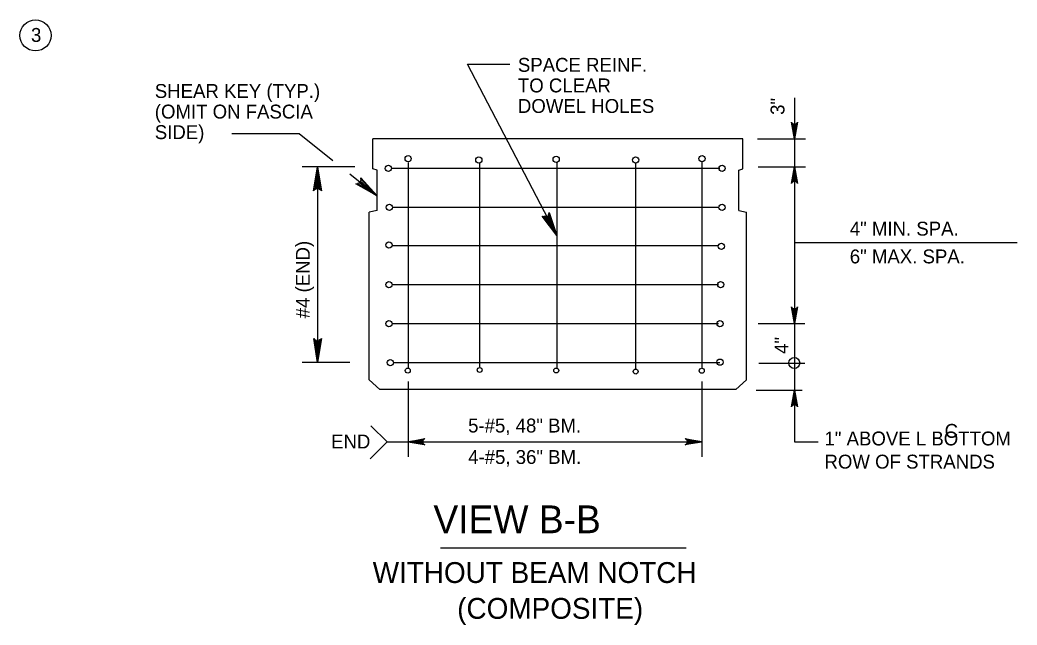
# Model space of a CAD drawing. Extents: x 639331 to 643089, y 299088 to 300975.
# Drawn here: x 639679.8 to 639895, y 300579.4 to 300710.1 of the extents above; entities that cross this region are included whole.
import ezdxf

# ---------------------------------------------------------------- set-up
doc = ezdxf.new("R2010")
doc.units = 0
doc.layers.add('1', color=7, linetype='Continuous')

msp = doc.modelspace()

# ---------------------------------------------------------------- linework, layer by layer
at = {"layer": '1'}
for p, q in [((639776.37, 300700.5), (639785.5, 300700.5)), ((639795.67, 300663.54), (639776.37, 300700.5)), ((639846.94, 300693.26), (639846.94, 300684.09)), ((639725.57, 300685.53), (639740.08, 300685.53)), ((639740.08, 300685.53), (639747.37, 300679.72)), ((639835.81, 300684.39), (639755.98, 300684.39)), ((639755.98, 300677.92), (639755.98, 300684.39)), ((639835.81, 300677.92), (639835.81, 300684.39)), ((639838.97, 300684.39), (639849.34, 300684.39)), ((639846.94, 300684.39), (639846.94, 300678.37)), ((639752.08, 300678.37), (639740.75, 300678.37)), ((639744.05, 300678.37), (639744.05, 300636.13)), ((639756.88, 300677.62), (639755.98, 300677.92)), ((639760, 300678.07), (639830.85, 300678.07)), ((639763.58, 300679.28), (639763.58, 300634.92)), ((639778.98, 300679.13), (639778.98, 300635.07)), ((639795.67, 300679.28), (639795.67, 300634.92)), ((639812.66, 300679.13), (639812.66, 300634.77)), ((639826.98, 300679.43), (639826.98, 300634.92)), ((639834.91, 300677.62), (639835.81, 300677.92)), ((639839.12, 300678.37), (639849.34, 300678.37)), ((639846.94, 300678.37), (639846.94, 300644.55)), ((639751.01, 300676.82), (639756.88, 300672.13)), ((639756.88, 300668.9), (639756.88, 300677.62)), ((639834.91, 300668.9), (639834.91, 300677.62)), ((639760.22, 300669.65), (639830.7, 300669.65)), ((639756.88, 300668.9), (639755.22, 300668.6)), ((639755.22, 300632.37), (639755.22, 300668.6)), ((639834.91, 300668.9), (639836.56, 300668.6)), ((639836.56, 300632.37), (639836.56, 300668.6)), ((639760.19, 300661.38), (639830.55, 300661.38)), ((639846.94, 300662), (639894.95, 300662)), ((639760.34, 300652.97), (639830.55, 300652.97)), ((639760.19, 300644.55), (639830.55, 300644.55)), ((639839.12, 300644.55), (639849.19, 300644.55)), ((639846.94, 300644.55), (639846.94, 300635.98)), ((639750.99, 300636.13), (639740.75, 300636.13)), ((639760.34, 300636.13), (639830.85, 300636.13)), ((639839.27, 300635.98), (639849.19, 300635.98)), ((639846.94, 300635.98), (639846.94, 300630.26)), ((639755.22, 300632.37), (639757.48, 300630.26)), ((639763.58, 300631.98), (639763.58, 300615.71)), ((639826.98, 300631.98), (639826.98, 300615.71)), ((639834.31, 300630.26), (639836.56, 300632.37)), ((639834.31, 300630.26), (639757.48, 300630.26)), ((639838.67, 300630.11), (639848.59, 300630.11)), ((639846.94, 300630.26), (639846.94, 300618.99)), ((639759.09, 300618.99), (639755.57, 300622.41)), ((639759.09, 300618.99), (639755.37, 300615.27)), ((639759.09, 300618.99), (639826.98, 300618.99)), ((639846.94, 300618.99), (639852.06, 300618.99)), ((639770.57, 300596.12), (639823.57, 300596.12))]:
    msp.add_line(p, q, dxfattribs=at)
for points in [[(639846.94, 300684.39), (639846.27, 300687.98), (639846.36, 300687.84), (639846.46, 300687.7), (639846.58, 300687.63), (639846.7, 300687.56), (639846.82, 300687.54), (639846.94, 300687.52), (639847.06, 300687.54), (639847.18, 300687.56), (639847.3, 300687.63), (639847.42, 300687.7), (639847.52, 300687.84), (639847.61, 300687.98), (639846.94, 300684.39), (639847.52, 300687.84), (639847.42, 300687.7), (639846.94, 300684.39), (639847.3, 300687.63), (639847.18, 300687.56), (639846.94, 300684.39), (639847.06, 300687.54), (639846.94, 300687.52), (639846.94, 300684.39), (639846.82, 300687.54), (639846.7, 300687.56), (639846.94, 300684.39), (639846.58, 300687.63), (639846.46, 300687.7), (639846.94, 300684.39), (639846.36, 300687.84)], [(639743.43, 300673.46), (639743.79, 300673.64), (639744.05, 300678.37), (639743.43, 300673.46), (639743.21, 300673.21), (639744.05, 300678.37), (639744.28, 300673.65), (639744.63, 300673.47), (639744.05, 300678.37), (639744.87, 300673.21), (639744.63, 300673.47)], [(639846.94, 300678.37), (639847.61, 300674.79), (639847.52, 300674.92), (639847.42, 300675.06), (639847.3, 300675.13), (639847.18, 300675.21), (639847.06, 300675.23), (639846.94, 300675.25), (639846.82, 300675.23), (639846.7, 300675.21), (639846.58, 300675.13), (639846.46, 300675.06), (639846.36, 300674.92), (639846.27, 300674.79), (639846.94, 300678.37), (639846.36, 300674.92), (639846.46, 300675.06), (639846.94, 300678.37), (639846.58, 300675.13), (639846.7, 300675.21), (639846.94, 300678.37), (639846.82, 300675.23), (639846.94, 300675.25), (639846.94, 300678.37), (639847.06, 300675.23), (639847.18, 300675.21), (639846.94, 300678.37), (639847.3, 300675.13), (639847.42, 300675.06), (639846.94, 300678.37), (639847.52, 300674.92)], [(639753.42, 300675.68), (639753.34, 300675.29), (639756.88, 300672.13), (639753.42, 300675.68), (639753.36, 300676.01), (639756.88, 300672.13), (639753.04, 300674.9), (639752.68, 300674.73), (639756.88, 300672.13), (639752.33, 300674.71), (639752.68, 300674.73)], [(639793.93, 300668.18), (639793.7, 300667.85), (639795.67, 300663.54), (639793.93, 300668.18), (639794.01, 300668.5), (639795.67, 300663.54), (639793.27, 300667.62), (639792.87, 300667.61), (639795.67, 300663.54), (639792.54, 300667.73), (639792.87, 300667.61)], [(639846.94, 300644.55), (639846.27, 300648.13), (639846.36, 300648), (639846.46, 300647.86), (639846.58, 300647.79), (639846.7, 300647.71), (639846.82, 300647.69), (639846.94, 300647.67), (639847.06, 300647.69), (639847.18, 300647.71), (639847.3, 300647.79), (639847.42, 300647.86), (639847.52, 300648), (639847.61, 300648.13), (639846.94, 300644.55), (639847.52, 300648), (639847.42, 300647.86), (639846.94, 300644.55), (639847.3, 300647.79), (639847.18, 300647.71), (639846.94, 300644.55), (639847.06, 300647.69), (639846.94, 300647.67), (639846.94, 300644.55), (639846.82, 300647.69), (639846.7, 300647.71), (639846.94, 300644.55), (639846.58, 300647.79), (639846.46, 300647.86), (639846.94, 300644.55), (639846.36, 300648)], [(639744.66, 300641.04), (639744.31, 300640.86), (639744.05, 300636.13), (639744.66, 300641.04), (639744.88, 300641.29), (639744.05, 300636.13), (639743.81, 300640.85), (639743.46, 300641.03), (639744.05, 300636.13), (639743.23, 300641.29), (639743.46, 300641.03)], [(639846.94, 300630.11), (639847.61, 300626.52), (639847.52, 300626.66), (639847.42, 300626.8), (639847.3, 300626.87), (639847.18, 300626.94), (639847.06, 300626.96), (639846.94, 300626.98), (639846.82, 300626.96), (639846.7, 300626.94), (639846.58, 300626.87), (639846.46, 300626.8), (639846.36, 300626.66), (639846.27, 300626.52), (639846.94, 300630.11), (639846.36, 300626.66), (639846.46, 300626.8), (639846.94, 300630.11), (639846.58, 300626.87), (639846.7, 300626.94), (639846.94, 300630.11), (639846.82, 300626.96), (639846.94, 300626.98), (639846.94, 300630.11), (639847.06, 300626.96), (639847.18, 300626.94), (639846.94, 300630.11), (639847.3, 300626.87), (639847.42, 300626.8), (639846.94, 300630.11), (639847.52, 300626.66)], [(639763.58, 300618.99), (639767.17, 300619.66), (639767.03, 300619.56), (639766.89, 300619.47), (639766.82, 300619.35), (639766.75, 300619.23), (639766.73, 300619.11), (639766.71, 300618.99), (639766.73, 300618.87), (639766.75, 300618.75), (639766.82, 300618.63), (639766.89, 300618.5), (639767.03, 300618.41), (639767.17, 300618.31), (639763.58, 300618.99), (639767.03, 300618.41), (639766.89, 300618.5), (639763.58, 300618.99), (639766.82, 300618.63), (639766.75, 300618.75), (639763.58, 300618.99), (639766.73, 300618.87), (639766.71, 300618.99), (639763.58, 300618.99), (639766.73, 300619.11), (639766.75, 300619.23), (639763.58, 300618.99), (639766.82, 300619.35), (639766.89, 300619.47), (639763.58, 300618.99), (639767.03, 300619.56)], [(639826.98, 300618.99), (639823.39, 300618.31), (639823.53, 300618.41), (639823.66, 300618.5), (639823.74, 300618.63), (639823.81, 300618.75), (639823.83, 300618.87), (639823.85, 300618.99), (639823.83, 300619.11), (639823.81, 300619.23), (639823.74, 300619.35), (639823.66, 300619.47), (639823.53, 300619.56), (639823.39, 300619.66), (639826.98, 300618.99), (639823.53, 300619.56), (639823.66, 300619.47), (639826.98, 300618.99), (639823.74, 300619.35), (639823.81, 300619.23), (639826.98, 300618.99), (639823.83, 300619.11), (639823.85, 300618.99), (639826.98, 300618.99), (639823.83, 300618.87), (639823.81, 300618.75), (639826.98, 300618.99), (639823.74, 300618.63), (639823.66, 300618.5), (639826.98, 300618.99), (639823.53, 300618.41)]]:
    msp.add_lwpolyline(points, dxfattribs=at)
for centre, radius in [((639683.2, 300706.74), 3.35), ((639763.59, 300680.14), 0.672), ((639778.84, 300679.84), 0.672), ((639795.53, 300679.99), 0.672), ((639812.67, 300679.84), 0.672), ((639826.99, 300680.14), 0.672), ((639759.33, 300678.03), 0.672), ((639831.31, 300678.03), 0.672), ((639759.55, 300669.62), 0.672), ((639831.31, 300669.62), 0.672), ((639759.45, 300661.5), 0.672), ((639831.16, 300661.2), 0.672), ((639759.45, 300652.93), 0.672), ((639831.01, 300652.93), 0.672), ((639759.45, 300644.51), 0.672), ((639830.86, 300644.51), 0.672), ((639830.86, 300636.18), 0.672), ((639846.89, 300636), 1.18), ((639759.75, 300636.09), 0.672), ((639763.52, 300634.36), 0.538), ((639779.02, 300634.49), 0.538), ((639795.55, 300634.38), 0.538), ((639826.93, 300634.33), 0.538), ((639812.68, 300634.15), 0.538)]:
    msp.add_circle(centre, radius, dxfattribs=at)

# ---------------------------------------------------------------- texts
for s, height, p in [('3', 3, (639682.23, 300705.34)), ('SPACE REINF.', 3, (639787.27, 300698.88)), ('TO CLEAR', 3, (639787.27, 300694.44)), ('SHEAR KEY (TYP.)', 3, (639708.94, 300693.24)), ('DOWEL HOLES', 3, (639787.27, 300690)), ('(OMIT ON FASCIA', 3, (639708.94, 300688.79)), ('SIDE)', 3, (639708.94, 300684.35)), ('4" MIN. SPA.', 3, (639858.87, 300663.51)), ('6" MAX. SPA.', 3, (639858.87, 300657.51)), ('5-#5, 48" BM.', 3, (639776.53, 300620.99)), ('C', 3, (639879.32, 300619.84)), ('END', 3, (639746.97, 300617.54)), ('1" ABOVE L BOTTOM', 3, (639853.41, 300618.2)), ('4-#5, 36" BM.', 3, (639776.54, 300614.2)), ('ROW OF STRANDS', 3, (639853.41, 300613.2)), (' VIEW B-B', 6, (639766.82, 300599.24)), ('WITHOUT BEAM NOTCH', 4.5, (639755.95, 300588.5)), ('(COMPOSITE)', 4.5, (639774.18, 300580.76))]:
    msp.add_text(s, height=height, dxfattribs=at).set_placement(p)
for s, p in [('3"', (639844.78, 300689.58)), ('#4 (END)', (639742.38, 300645.66)), ('4"', (639845.64, 300637.97))]:
    msp.add_text(s, height=3, rotation=90, dxfattribs=at).set_placement(p)

doc.saveas('drawing.dxf')
